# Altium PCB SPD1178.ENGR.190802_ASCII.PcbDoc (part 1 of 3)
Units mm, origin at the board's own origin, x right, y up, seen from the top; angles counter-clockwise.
Board outline 150 x 150 mm, 2 copper layers (Top Layer, Bottom Layer); 315 components, 164 nets, 838 pads, 882 vias.
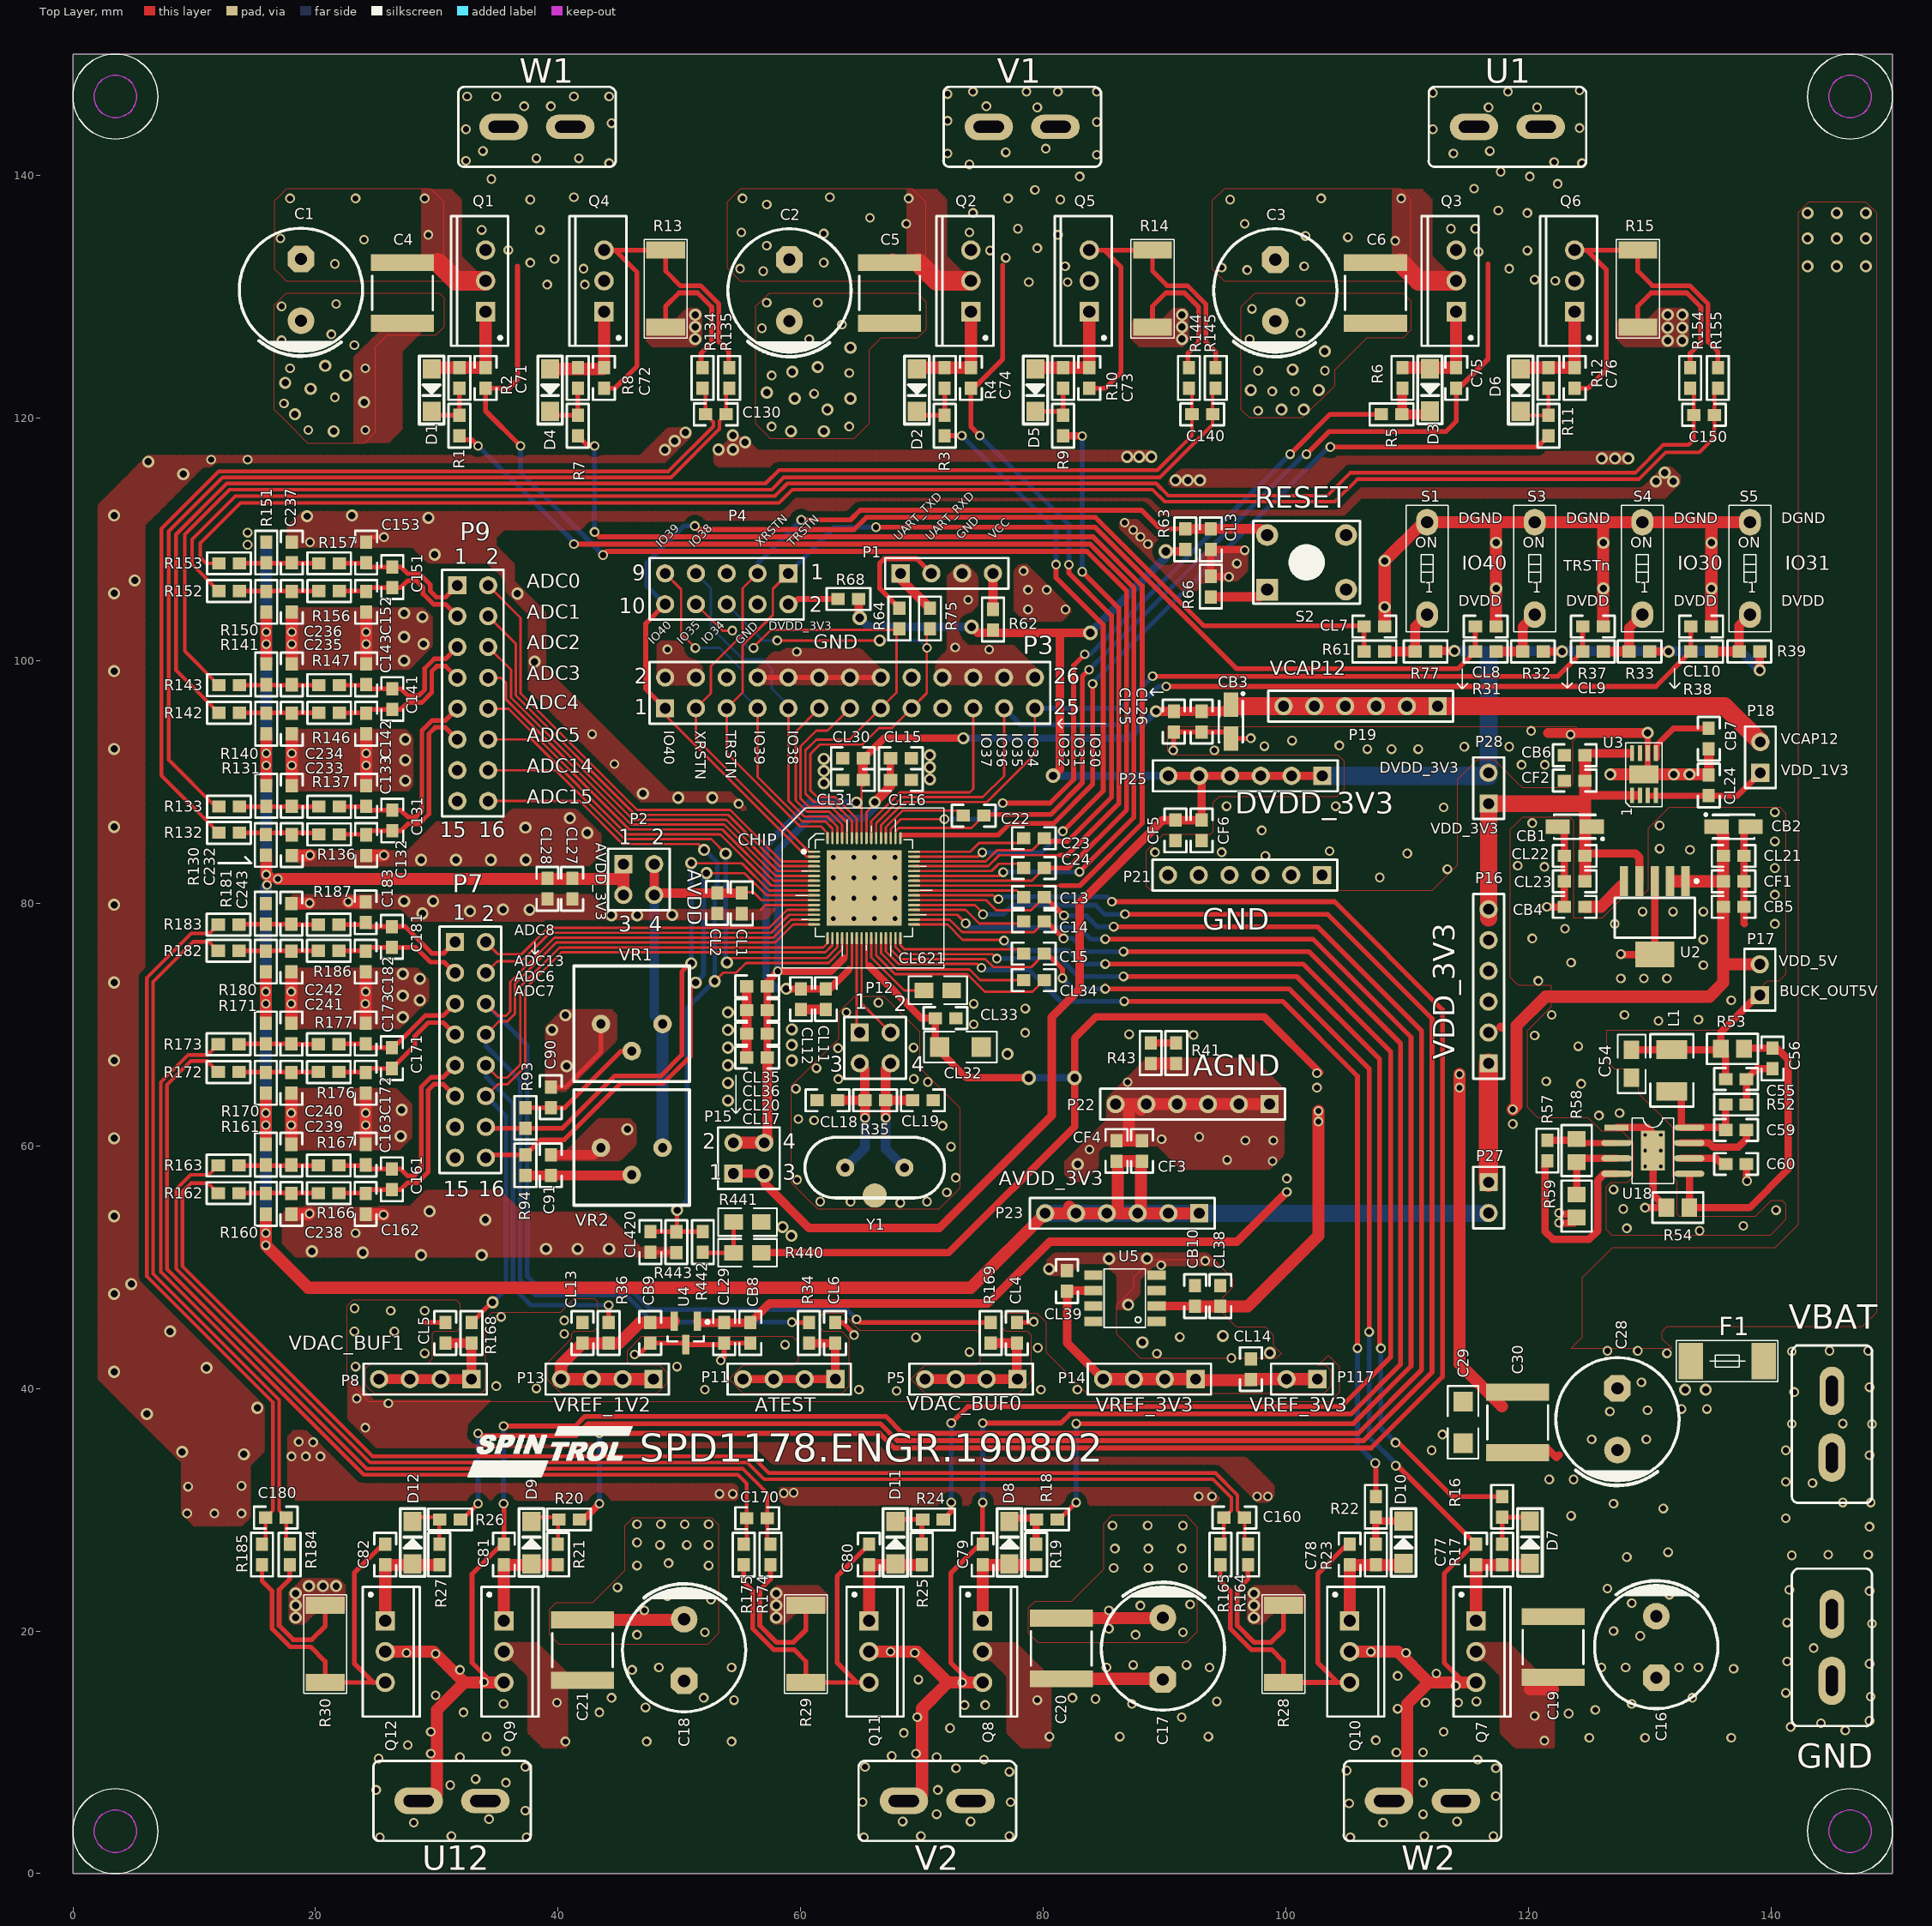
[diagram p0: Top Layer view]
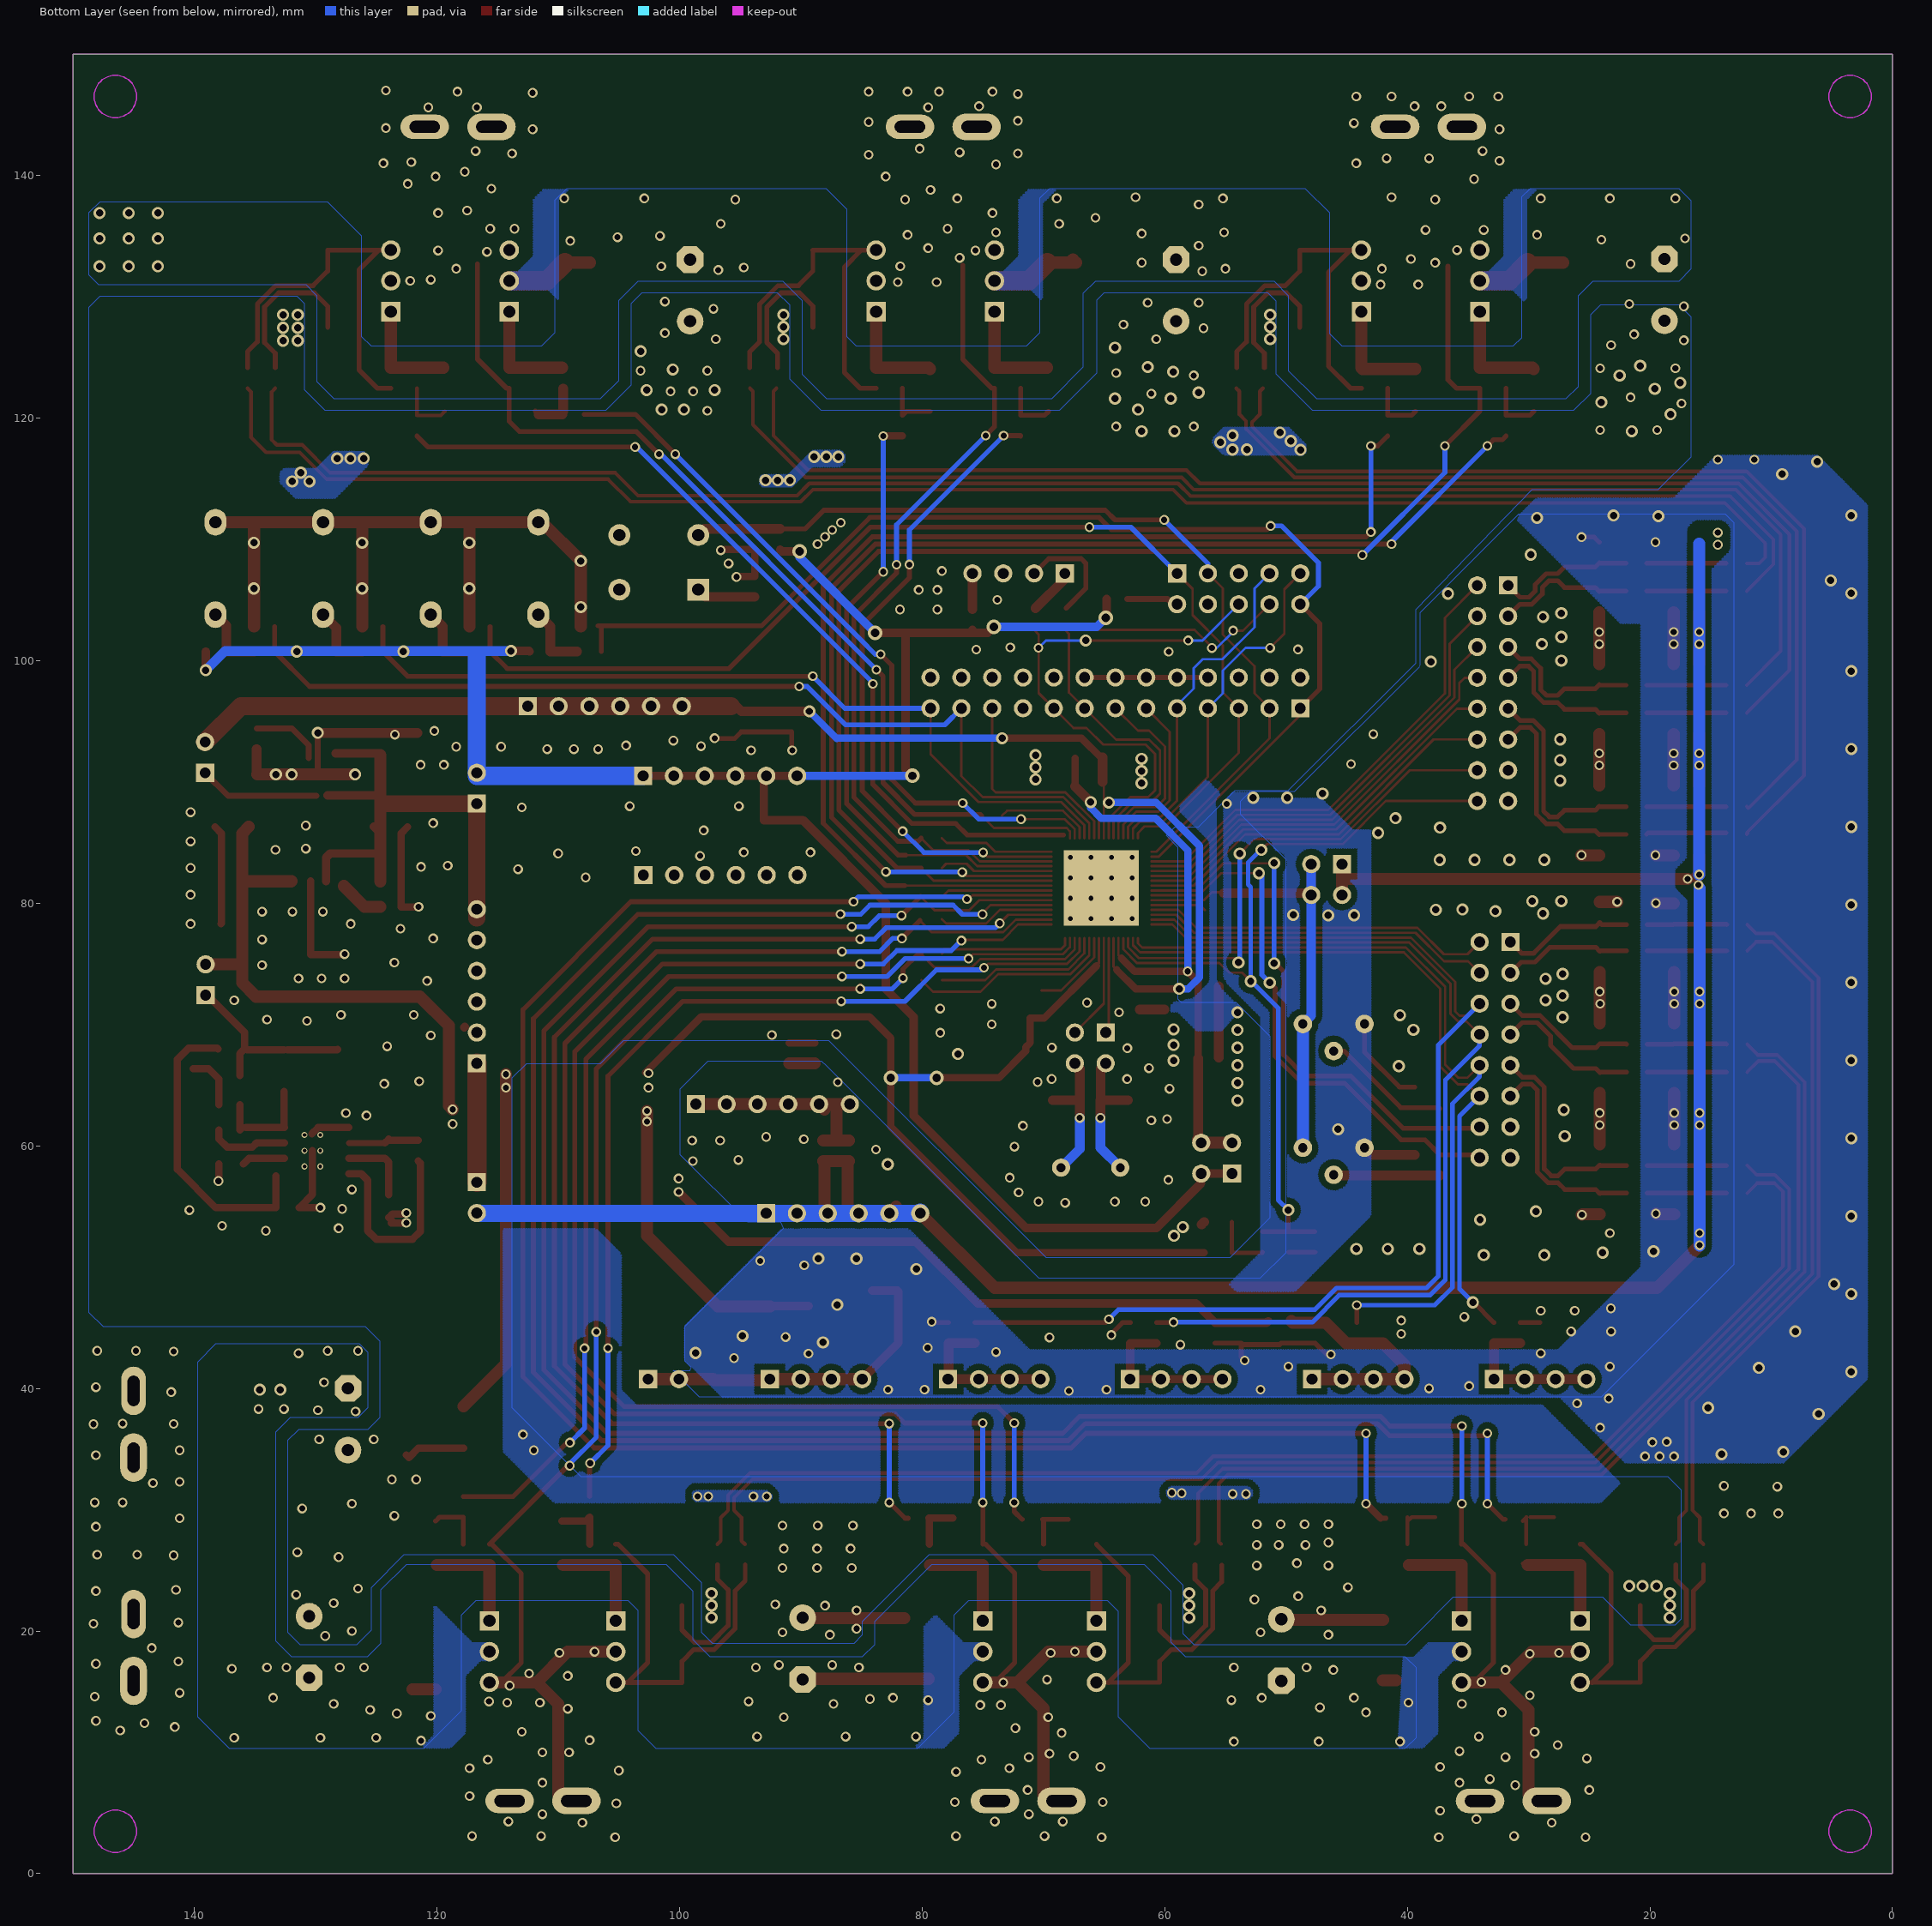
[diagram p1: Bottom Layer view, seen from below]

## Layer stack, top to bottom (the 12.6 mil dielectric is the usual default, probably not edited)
Top Solder: solder mask 0.0102, Solder Resist, Dk 3.5
Top Layer: signal copper 0.0356
Dielectric1: dielectric 0.32, FR-4, Dk 4.8
Bottom Layer: signal copper 0.0356
Bottom Solder: solder mask 0.0102, Solder Resist, Dk 3.5

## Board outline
0,0 0,150 150,150 150,0

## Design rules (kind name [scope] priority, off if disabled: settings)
AssemblyTestPointUsage [All] p0: scope1count=1 scope1_0_kind=Board scope1_0_value=Board scope2count=1 scope2_0_kind=Board scope2_0_value=Board commentlength=0
AssemblyTestpoint [All] p0: scope1count=1 scope1_0_kind=Board scope1_0_value=Board scope2count=1 scope2_0_kind=Board scope2_0_value=Board commentlength=0
Clearance 1 [All] p0: scope1count=1 scope1_0_kind=Board scope1_0_value=Board scope2count=1 scope2_0_kind=Board scope2_0_value=Board commentlength=0 gap=0.2
Clearance poly [All] p0 off: scope1count=1 scope1_0_kind=Board scope1_0_value=Board scope2count=1 scope2_0_kind=Board scope2_0_value=Board commentlength=48 gap=0.5 // Protel DXP Scope 1 Expression Was: InPolygon
Clearance [All] p0 off: scope1count=1 scope1_0_kind=Board scope1_0_value=Board scope2count=1 scope2_0_kind=Footprint scope2_0_value=OSC commentlength=60 gap=1.2 // Protel DXP Scope 1 Expression Was: InNamedPolygon('OSC')
Clearance [InNamedPolygon('OSC') vs HasFootprint('OSC')] p1: gap=1.2 ignorepadtopadclearanceinfootprint=FALSE except(0: Arc-Hole Track-Hole SMDPad-Hole THPad-Hole Via-Hole Fill-Hole Poly-Hole Region-Hole Text-Hole)
Clearance poly [InPolygon] p2: gap=0.5 ignorepadtopadclearanceinfootprint=FALSE except(0: Arc-Hole Track-Hole SMDPad-Hole THPad-Hole Via-Hole Fill-Hole Poly-Hole Region-Hole Text-Hole)
Clearance 1 [All] p3: gap=0.2 ignorepadtopadclearanceinfootprint=FALSE except(0: Arc-Hole Track-Hole SMDPad-Hole THPad-Hole Via-Hole Fill-Hole Poly-Hole Region-Hole Text-Hole)
ComponentClearance [All] p0 off: scope1count=1 scope1_0_kind=Board scope1_0_value=Board scope2count=1 scope2_0_kind=Board scope2_0_value=Board commentlength=0 gap=0.254 collisioncheckmode=3
ComponentClearance [All] p1 off: gap=0.254 collisioncheckmode=3 verticalgap=0.254 showdistances=FALSE
DiffPairsRouting [All] p0: scope1count=1 scope1_0_kind=Board scope1_0_value=Board scope2count=1 scope2_0_kind=Board scope2_0_value=Board commentlength=0
DiffPairsRouting [All] p1: maxlimit=1 minlimit=0.2 mostfreqgap=0.2 toplayer_minwidth=0.381 toplayer_maxwidth=0.381 toplayer_prefwidth=0.381 bottomlayer_minwidth=0.381 bottomlayer_maxwidth=0.381 bottomlayer_prefwidth=0.381 maxuncoupledlength=12.7
FabricationTestPointUsage [All] p0: scope1count=1 scope1_0_kind=Board scope1_0_value=Board scope2count=1 scope2_0_kind=Board scope2_0_value=Board commentlength=0 valid=0 allowmultiple=FALSE
FabricationTestpoint [All] p0: scope1count=1 scope1_0_kind=Board scope1_0_value=Board scope2count=1 scope2_0_kind=Board scope2_0_value=Board commentlength=0 side=3 testpointundercomponent=TRUE minsize=1.016 maxsize=2.54 preferedsize=1.524 minholesize=0 maxholesize=1.016 preferedholesize=0.813 testpointgrid=0.025
FanoutControl Fanout_BGA [All] p0 off: scope1count=1 scope1_0_kind=Board scope1_0_value=Board scope2count=1 scope2_0_kind=Board scope2_0_value=Board commentlength=69 // Protel DXP Scope 1 Expression Was: IsBGA   Fanout_BGA (Default Rule)
FanoutControl Fanout_LCC [All] p0 off: scope1count=1 scope1_0_kind=Board scope1_0_value=Board scope2count=1 scope2_0_kind=Board scope2_0_value=Board commentlength=69 // Protel DXP Scope 1 Expression Was: IsLCC   Fanout_LCC (Default Rule)
FanoutControl Fanout_SOIC [All] p0 off: scope1count=1 scope1_0_kind=Board scope1_0_value=Board scope2count=1 scope2_0_kind=Board scope2_0_value=Board commentlength=71 // Protel DXP Scope 1 Expression Was: IsSOIC   Fanout_SOIC (Default Rule)
FanoutControl Fanout_Small [All] p0 off: scope1count=1 scope1_0_kind=Board scope1_0_value=Board scope2count=1 scope2_0_kind=Board scope2_0_value=Board commentlength=84 // Protel DXP Scope 1 Expression Was: (CompPinCount < 5)   Fanout_Small (Default Rule)
FanoutControl Fanout_Default [All] p0: scope1count=1 scope1_0_kind=Board scope1_0_value=Board scope2count=1 scope2_0_kind=Board scope2_0_value=Board commentlength=30 // Fanout_Default (Default Rule)
FanoutControl Fanout_Small [All] p1 off: bgadir=Out bgaviamode=Centered fanoutstyle=Auto fanoutdirection=Alternating viagrid=0.025 // Protel DXP Scope 1 Expression Was: (CompPinCount < 5)   Fanout_Small (Default Rule)
FanoutControl Fanout_Default [All] p2: bgadir=Out bgaviamode=Centered fanoutstyle=Auto fanoutdirection=Alternating viagrid=0.025 // Fanout_Default (Default Rule)
FanoutControl Fanout_SOIC [All] p3 off: bgadir=Out bgaviamode=Centered fanoutstyle=Auto fanoutdirection=Alternating viagrid=0.025 // Protel DXP Scope 1 Expression Was: IsSOIC   Fanout_SOIC (Default Rule)
FanoutControl Fanout_BGA [All] p4 off: bgadir=Out bgaviamode=Centered fanoutstyle=Auto fanoutdirection=Alternating viagrid=0.025 // Protel DXP Scope 1 Expression Was: IsBGA   Fanout_BGA (Default Rule)
FanoutControl Fanout_LCC [All] p5 off: bgadir=Out bgaviamode=Centered fanoutstyle=Auto fanoutdirection=Alternating viagrid=0.025 // Protel DXP Scope 1 Expression Was: IsLCC   Fanout_LCC (Default Rule)
Height [All] p0 off: scope1count=1 scope1_0_kind=Board scope1_0_value=Board scope2count=1 scope2_0_kind=Board scope2_0_value=Board commentlength=0
Height [All] p1 off: minheight=0 maxheight=25.4 prefheight=12.7
HoleSize [All] p0: scope1count=1 scope1_0_kind=Board scope1_0_value=Board scope2count=1 scope2_0_kind=Board scope2_0_value=Board commentlength=0 absolutevalues=TRUE maxlimit=5 minlimit=0.025 maxpercent=80.000 minpercent=20.000
HoleSize [All] p1: absolutevalues=TRUE maxlimit=5 minlimit=0.025 maxpercent=80.000 minpercent=20.000
HoleToHoleClearance [All] p0 off: scope1count=1 scope1_0_kind=Board scope1_0_value=Board scope2count=1 scope2_0_kind=Board scope2_0_value=Board commentlength=0
HoleToHoleClearance [All] p1 off: gap=0 allowstackedmicrovias=FALSE
LayerPairs [All] p0: scope1count=1 scope1_0_kind=Board scope1_0_value=Board scope2count=1 scope2_0_kind=Board scope2_0_value=Board commentlength=0 enforce=TRUE
MinimumSolderMaskSliver [All] p0 off: scope1count=1 scope1_0_kind=Board scope1_0_value=Board scope2count=1 scope2_0_kind=Board scope2_0_value=Board commentlength=0
MinimumSolderMaskSliver [All] p1 off: minsoldermaskwidth=0.254
NetAntennae [All] p0: scope1count=1 scope1_0_kind=Board scope1_0_value=Board scope2count=1 scope2_0_kind=Board scope2_0_value=Board commentlength=0
PasteMaskExpansion [All] p0: scope1count=1 scope1_0_kind=Board scope1_0_value=Board scope2count=1 scope2_0_kind=Board scope2_0_value=Board commentlength=0 expansion=0
PlaneClearance [All] p0 off: scope1count=1 scope1_0_kind=Board scope1_0_value=Board scope2count=1 scope2_0_kind=Board scope2_0_value=Board commentlength=0 clearance=0.508
PlaneClearance [All] p1 off: clearance=0.508
PlaneConnect [All] p0: scope1count=1 scope1_0_kind=Board scope1_0_value=Board scope2count=1 scope2_0_kind=Board scope2_0_value=Board commentlength=0 planeconnectstyle=Direct reliefexpansion=0.508 reliefentries=4 reliefconductorwidth=0.254 reliefairgap=0.254
PlaneConnect [All] p1: planeconnectstyle=Direct reliefexpansion=0.508 reliefentries=4 reliefconductorwidth=0.254 reliefairgap=0.254
PolygonConnect [All] p0: scope1count=1 scope1_0_kind=Board scope1_0_value=Board scope2count=1 scope2_0_kind=Board scope2_0_value=Board commentlength=0 connectstyle=Direct reliefconductorwidth=0.254 reliefentries=4 polygonreliefangle="90 Angle"
PolygonConnect [All] p1: connectstyle=Direct reliefconductorwidth=0.254 reliefentries=4 polygonreliefangle="90 Angle" airgapwidth=0.254
RoutingCorners [All] p0: scope1count=1 scope1_0_kind=Board scope1_0_value=Board scope2count=1 scope2_0_kind=Board scope2_0_value=Board commentlength=0 cornerstyle=45-Degree minsetback=2.54 maxsetback=2.54
RoutingLayers [All] p0: scope1count=1 scope1_0_kind=Board scope1_0_value=Board scope2count=1 scope2_0_kind=Board scope2_0_value=Board commentlength=0 top layer=Automatic bottom layer=Automatic
RoutingPriority [All] p1: routingpriority=4
RoutingPriority [All] p4: scope1count=1 scope1_0_kind=Board scope1_0_value=Board scope2count=1 scope2_0_kind=Board scope2_0_value=Board commentlength=0
RoutingTopology [All] p0: scope1count=1 scope1_0_kind=Board scope1_0_value=Board scope2count=1 scope2_0_kind=Board scope2_0_value=Board commentlength=0 topology=Shortest
RoutingVias [All] p0: scope1count=1 scope1_0_kind=Board scope1_0_value=Board scope2count=1 scope2_0_kind=Board scope2_0_value=Board commentlength=0 holewidth=0.4 width=0.8 viastyle="Through Hole" minholewidth=0.1 minwidth=0.6 maxholewidth=2 maxwidth=3
RoutingVias [All] p1: holewidth=0.4 width=0.8 viastyle="Through Hole" minholewidth=0.1 minwidth=0.6 maxholewidth=2 maxwidth=3
ShortCircuit [All] p0: scope1count=1 scope1_0_kind=Board scope1_0_value=Board scope2count=1 scope2_0_kind=Board scope2_0_value=Board commentlength=0 allowed=FALSE
SilkToBoardRegionClearance [All] p0: scope1count=1 scope1_0_kind=Board scope1_0_value=Board scope2count=1 scope2_0_kind=Board scope2_0_value=Board commentlength=0
SilkToSilkClearance [All] p0 off: scope1count=1 scope1_0_kind=Board scope1_0_value=Board scope2count=1 scope2_0_kind=Board scope2_0_value=Board commentlength=0
SilkToSilkClearance [All] p1 off: silktosilkclearance=0.254
SilkToSolderMaskClearance SilkscreenOverComponentPads [All] p0 off: scope1count=1 scope1_0_kind=Board scope1_0_value=Board scope2count=1 scope2_0_kind=Board scope2_0_value=Board commentlength=44 // Protel DXP Scope 1 Expression Was: IsPad
SilkToSolderMaskClearance SilkscreenOverComponentPads [IsPad] p1 off: minsilkscreentomaskgap=0.254 clearancetoexposedcopper=TRUE
SolderMaskExpansion [All] p0: scope1count=1 scope1_0_kind=Board scope1_0_value=Board scope2count=1 scope2_0_kind=Board scope2_0_value=Board commentlength=0 expansion=0.102
SolderMaskExpansion [All] p1: expansion=0.102 istentingtop=FALSE
UnRoutedNet [All] p0: scope1count=1 scope1_0_kind=Board scope1_0_value=Board scope2count=1 scope2_0_kind=Board scope2_0_value=Board commentlength=0
UnpouredPolygon [All] p0: scope1count=1 scope1_0_kind=Board scope1_0_value=Board scope2count=1 scope2_0_kind=Board scope2_0_value=Board commentlength=0
Width [All] p0: scope1count=1 scope1_0_kind=Board scope1_0_value=Board scope2count=1 scope2_0_kind=Board scope2_0_value=Board commentlength=0 maxlimit=5 minlimit=0.2 preferedwidth=0.4
Width [All] p1: maxlimit=5 minlimit=0.2 preferedwidth=0.4
14 further rules are at their usual default settings.

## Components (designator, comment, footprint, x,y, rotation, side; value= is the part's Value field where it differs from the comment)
C1 "47uF/160V" RB5.0/10 18.8,133.1 r90 top
C2 "47uF/160V" RB5.0/10 59.068,133.05 r90 top
C3 "47uF/160V" RB5.0/10 99.119,133.05 r90 top
C4 "2.2uF/250V" 2220 27.17,130.307 r270 top
C5 "2.2uF/250V" 2220 67.323,130.307 r270 top
C6 "2.2uF/250V" 2220 107.374,130.307 r270 top
C13 "100nF/100V" C0603[1608] 79.22,80.5 r0 top
C14 "100nF/100V" C0603[1608] 79.22,78.51 r0 top
C15 "100nF/100V" C0603[1608] 79.21,75.85 r0 top
C16 "47uF/160V" RB5.0/10 130.523,16.145 r270 top
C17 "47uF/160V" RB5.0/10 89.853,16.018 r270 top
C18 "47uF/160V" RB5.0/10 50.386,15.891 r270 top
C19 "2.2uF/250V" 2220 122.014,18.685 r90 top
C20 "2.2uF/250V" 2220 81.471,18.558 r90 top
C21 "2.2uF/250V" 2220 42.004,18.431 r90 top
C22 "100nF/100V" C0603[1608] 74.25,87.22 r0 top
C23 "100nF/100V" C0603[1608] 79.22,85.36 r0 top
C24 "100nF/100V" C0603[1608] 79.22,82.9 r0 top
C28 "47uF/160V" RB5.0/10 127.323,40 r90 top
C29 "47nF/200V" 1206 114.6,37.2 r270 top
C30 "2.2uF/250V" 2220 119.1,37.2 r270 top
C54 "22uF" 0805 128.49,66.76 r270 top
C55 "470pF" C0603[1608] 137.1,65.5 r180 top
C56 "10nF" C0603[1608] 140.1,67.2 r90 top
C59 "10nF" C0603[1608] 137.1,61.3 r180 top
C60 "1uF/16V" C0603[1608] 137.1,58.5 r180 top
C71 "1nF" C0603[1608] 34.019,123.301 r270 top
C72 "1nF" C0603[1608] 43.782,123.301 r270 top
C73 "1nF" C0603[1608] 83.787,123.301 r270 top
C74 "1nF" C0603[1608] 74.024,123.301 r270 top
C75 "1nF" C0603[1608] 114.029,123.301 r270 top
C76 "1nF" C0603[1608] 123.792,123.301 r270 top
C77 "1nF" C0603[1608] 115.664,26.305 r90 top
C78 "1nF" C0603[1608] 105.25,26.305 r90 top
C79 "1nF" C0603[1608] 74.994,26.305 r90 top
C80 "1nF" C0603[1608] 65.626,26.305 r90 top
C81 "1nF" C0603[1608] 35.527,26.305 r90 top
C82 "1nF" C0603[1608] 25.748,26.305 r90 top
C90 "100nF" C0603[1608] 39.4,64 r270 top
C91 "100nF" C0603[1608] 39.4,58.4 r270 top
C130 "1nF" C0603[1608] 53,120.3 r180 top
C131 "22pF" C0603[1608] 26.331,86.819 r270 top
C132 "22pF" C0603[1608] 24.172,84.787 r270 top
C133 "22pF" C0603[1608] 24.172,88.851 r90 top
C140 "1nF" C0603[1608] 93.1,120.3 r180 top
C141 "22pF" C0603[1608] 26.331,96.833 r270 top
C142 "22pF" C0603[1608] 24.172,94.801 r270 top
C143 "22pF" C0603[1608] 24.172,98.865 r90 top
C150 "1nF" C0603[1608] 134.463,120.253 r180 top
C151 "22pF" C0603[1608] 26.331,106.874 r270 top
C152 "22pF" C0603[1608] 24.172,104.842 r270 top
C153 "22pF" C0603[1608] 24.172,108.906 r90 top
C160 "1nF" C0603[1608] 95.741,29.353 r0 top
C161 "22pF" C0603[1608] 26.293,57.24 r270 top
C162 "22pF" C0603[1608] 24.134,55.208 r270 top
C163 "22pF" C0603[1608] 24.134,59.272 r90 top
C170 "1nF" C0603[1608] 56.4,29.3 r0 top
C171 "22pF" C0603[1608] 26.293,67.227 r270 top
C172 "22pF" C0603[1608] 24.134,65.195 r270 top
C173 "22pF" C0603[1608] 24.134,69.259 r90 top
C180 "1nF" C0603[1608] 16.731,29.353 r0 top
C181 "22pF" C0603[1608] 26.293,77.222 r270 top
C182 "22pF" C0603[1608] 24.134,75.19 r270 top
C183 "22pF" C0603[1608] 24.134,79.254 r90 top
C232 "22pF" C0603[1608] 18.042,84.787 r270 top
C233 "22pF" C0603[1608] 18.042,88.851 r270 top
C234 "22pF" C0603[1608] 18.042,94.801 r270 top
C235 "22pF" C0603[1608] 18.042,98.86 r270 top
C236 "22pF" C0603[1608] 18.042,104.842 r270 top
C237 "22pF" C0603[1608] 18.042,108.906 r270 top
C238 "22pF" C0603[1608] 18.004,55.208 r270 top
C239 "22pF" C0603[1608] 18.004,59.272 r270 top
C240 "22pF" C0603[1608] 18.004,65.195 r270 top
C241 "22pF" C0603[1608] 18.004,69.259 r270 top
C242 "22pF" C0603[1608] 18.004,75.19 r270 top
C243 "22pF" C0603[1608] 18.004,79.127 r270 top
CB1 "10uF/10V" TC3216-A 123.8,86.3 r180 top
CB2 "10uF/10V" TC3216-A 136.9,86.3 r0 top
CB3 "10uF/10V" TC3216-A 95.455,94.968 r270 top
CB4 "10nF" C0603[1608] 123.8,79.7 r180 top
CB5 "2.2uF/10V" C0603[1608] 136.9,79.7 r0 top
CB6 "2.2uF/10V" C0603[1608] 123.8,92.2 r180 top
CB7 "10nF" C0603[1608] 134.85,93.56 r270 top
CB8 "100nF" C0603[1608] 55.847,44.577 r90 top
CB9 "100nF" C0603[1608] 47.592,44.577 r90 top
CB10 "100nF" C0603[1608] 92.506,47.614 r270 top
CF1 "100nF" C0603[1608] 136.9,81.8 r0 top
CF2 "100nF" C0603[1608] 123.8,90.1 r180 top
CF3 "100nF" C0603[1608] 88.13,59.58 r90 top
CF4 "2.2uF/10V" C0603[1608] 86.03,59.58 r90 top
CF5 "100nF" C0603[1608] 90.883,86.003 r270 top
CF6 "2.2uF/10V" C0603[1608] 93.042,86.003 r270 top
CHIP "SPD1098D" QFN64L_201707 65.22,81.25 r0 top
CL1 "4.7uF/10V" C0603[1608] 55.133,79.987 r90 top
CL2 "100nF" C0603[1608] 53.11,80.01 r90 top
CL3 "1uF/16V" C0603[1608] 93.8,110 r90 top
CL4 "100nF" C0603[1608] 77.818,44.577 r90 top
CL5 "100nF" C0603[1608] 30.701,44.577 r90 top
CL6 "100nF" C0603[1608] 62.832,44.577 r90 top
CL7 "" C0603[1608] 107.29,102.81 r0 top
CL8 "100nF" C0603[1608] 116.46,102.81 r0 top
CL9 "100nF" C0603[1608] 125.3,102.81 r0 top
CL10 "100nF" C0603[1608] 134.22,102.81 r0 top
CL11 "22nF/50V" C0603[1608] 62.07,72.09 r90 top
CL12 "2.2uF/10V" C0603[1608] 60.02,72.09 r90 top
CL13 "100nF" C0603[1608] 42.004,44.577 r270 top
CL14 "100nF" C0603[1608] 97.11,41.59 r270 top
CL15 "4.7uF/10V" C0603[1608] 68.25,91.95 r180 top
CL16 "100nF" C0603[1608] 68.25,90.16 r180 top
CL17 "4.7uF/10V" C0603[1608] 56.4,67.28 r0 top
CL18 "20pF" C0603[1608] 62.197,63.754 r0 top
CL19 "20pF" C0603[1608] 70.071,63.754 r180 top
CL20 "100nF" C0603[1608] 56.4,69.235 r0 top
CL21 "4.7uF/10V" C0603[1608] 136.9,83.9 r0 top
CL22 "4.7uF/10V" C0603[1608] 123.8,83.9 r180 top
CL23 "4.7uF/10V" C0603[1608] 123.8,81.8 r180 top
CL24 "4.7uF/10V" C0603[1608] 134.85,89.71 r90 top
CL25 "100nF" C0603[1608] 90.756,94.968 r270 top
CL26 "100nF" C0603[1608] 93.042,94.968 r270 top
CL27 "2.2uF" C0603[1608] 41.165,81.19 r90 top
CL28 "10nF" C0603[1608] 39.12,81.19 r90 top
CL29 "1uF/16V" C0603[1608] 53.688,44.577 r90 top
CL30 "10nF" C0603[1608] 64.3,91.95 r0 top
CL31 "100nF" C0603[1608] 64.3,90.16 r0 top
CL32 "2.2uF/100V" 1206 73.16,68.14 r180 top
CL33 "100nF/100V" C0603[1608] 71.93,70.52 r180 top
CL34 "22nF/50V" C0603[1608] 79.215,73.66 r0 top
CL35 "4.7uF/10V" C0603[1608] 56.4,73.145 r0 top
CL36 "100nF" C0603[1608] 56.4,71.19 r0 top
CL38 "1uF/16V" C0603[1608] 94.586,47.614 r270 top
CL39 "1uF/16V" C0603[1608] 81.95,48.85 r270 top
CL420 "1nF" C0603[1608] 47.608,52.07 r90 top
CL621 "2.2uF/30V" 0805 71.3,72.82 r180 top
D1 "IN4148W-E3-08" LL-34 29.574,122.285 r90 top
D2 "IN4148W-E3-08" LL-34 69.579,122.285 r90 top
D3 "IN4148W-E3-08" LL-34 111.87,122.3 r90 top
D4 "IN4148W-E3-08" LL-34 39.337,122.285 r90 top
D5 "IN4148W-E3-08" LL-34 79.342,122.285 r90 top
D6 "IN4148W-E3-08" LL-34 119.347,122.285 r90 top
D7 "IN4148W-E3-08" LL-34 120.109,27.321 r270 top
D8 "IN4148W-E3-08" LL-34 77.2,27.3 r270 top
D9 "IN4148W-E3-08" LL-34 37.8,27.3 r270 top
D10 "IN4148W-E3-08" LL-34 109.695,27.321 r270 top
D11 "IN4148W-E3-08" LL-34 67.8,27.3 r270 top
D12 "IN4148W-E3-08" LL-34 28,27.3 r270 top
F1 "36V/30A" F3 139.38,42.26 r180 top
GND "250插片" PIN_L 145,21.4 r270 top
L1 "47uH 1.0A" 1210R 131.8,64.5 r90 top
P1 "单排插座2.54*4" HDR1X4 68.225,107.188 r0 top
P2 "双排插针2.54*2" HDR2X2 45.38,83.22 r270 top
P3 "双排插针2.54*13" HDR2X13 48.818,96.069 r0 top
P4 "双排插针2.54*5" HDR2X5 58.978,107.188 r180 top locked
P5 "单排插针2.54*4" HDR1X4 77.857,40.767 r180 top
P7 "双排插针2.54*8" HDR2X8 31.5,76.8 r270 top
P8 "单排插针2.54*4" HDR1X4 32.857,40.767 r180 top
P9 "双排插针2.54*8" HDR2X8 31.692,106.2 r270 top
P11 "单排插针2.54*4" HDR1X4 62.857,40.767 r180 top
P12 "双排插针2.54*2" HDR2X2 64.864,69.342 r270 top
P13 "单排插针2.54*4" HDR1X4 47.857,40.767 r180 top
P14 "单排插针2.54*4" HDR1X4 92.55,40.767 r180 top
P15 "双排插针2.54*2" HDR2X2 54.45,57.71 r0 top
P16 "单排插针2.54*6" HDR1X6 116.7,66.8 r90 top
P17 "单排插针2.54*2" HDR1X2 139.06,72.421 r90 top
P18 "单排插针2.54*2" HDR1X2 139.105,90.75 r90 top
P19 "单排插针2.54*6" HDR1X6 112.5,96.24 r180 top
P21 "单排插针2.54*6" HDR1X6 102.97,82.32 r180 top
P22 "单排插针2.54*6" HDR1X6 98.65,63.44 r180 top
P23 "单排插针2.54*6" HDR1X6 92.85,54.44 r180 top
P25 "单排插针2.54*6" HDR1X6 103,90.5 r180 top
P27 "单排插针2.54*2" HDR1X2 116.7,57 r270 top
P28 "单排插针2.54*2" HDR1X2 116.7,88.21 r90 top
P117 "单排插针2.54*2" HDR1X2 102.583,40.767 r180 top
Q1 "IRF1010E" TO-220AB 34.019,131.302 r90 top
Q2 "IRF1010E" TO-220AB 74.024,131.302 r90 top
Q3 "IRF1010E" TO-220AB 114.029,131.302 r90 top
Q4 "IRF1010E" TO-220AB 43.782,131.302 r90 top
Q5 "IRF1010E" TO-220AB 83.787,131.302 r90 top
Q6 "IRF1010E" TO-220AB 123.792,131.302 r90 top
Q7 "IRF1010E" TO-220AB 115.664,18.304 r270 top
Q8 "IRF1010E" TO-220AB 74.994,18.304 r270 top
Q9 "IRF1010E" TO-220AB 35.527,18.304 r270 top
Q10 "IRF1010E" TO-220AB 105.25,18.304 r270 top
Q11 "IRF1010E" TO-220AB 65.626,18.304 r270 top
Q12 "IRF1010E" TO-220AB 25.748,18.304 r270 top
R1 "22R" R0603[1608] 31.86,119.364 r90 top
R2 "22R" R0603[1608] 31.86,123.301 r90 top
R3 "22R" R0603[1608] 71.865,119.364 r90 top
R4 "22R" R0603[1608] 71.865,123.301 r90 top
R5 "22R" R0603[1608] 108.7,120.3 r0 top
R6 "22R" R0603[1608] 109.6,123.3 r90 top
R7 "22R" R0603[1608] 41.623,119.364 r90 top
R8 "22R" R0603[1608] 41.623,123.301 r90 top
R9 "22R" R0603[1608] 81.628,119.364 r90 top
R10 "22R" R0603[1608] 81.628,123.301 r90 top
R11 "22R" R0603[1608] 121.633,119.364 r90 top
R12 "22R" R0603[1608] 121.633,123.301 r90 top
R13 "0.005R /1W 1% 50ppm" 2512 48.862,130.667 r90 top
R14 "0.005R /1W 1% 50ppm" 2512 88.994,130.667 r90 top
R15 "0.005R /1W 1% 50ppm" 2512 128.999,130.667 r90 top
R16 "22R" R0603[1608] 117.823,30.242 r270 top
R17 "22R" R0603[1608] 117.823,26.305 r270 top
R18 "22R" R0603[1608] 80.3,29.2 r180 top
R19 "22R" R0603[1608] 79.4,26.3 r270 top
R20 "22R" R0603[1608] 40.9,29.2 r180 top
R21 "22R" R0603[1608] 39.986,26.305 r270 top
R22 "22R" R0603[1608] 107.409,30.242 r270 top
R23 "22R" R0603[1608] 107.409,26.305 r270 top
R24 "22R" R0603[1608] 70.9,29.2 r180 top
R25 "22R" R0603[1608] 69.985,26.305 r270 top
R26 "22R" R0603[1608] 31.1,29.2 r180 top
R27 "22R" R0603[1608] 30.207,26.305 r270 top
R28 "0.005R /1W 1% 50ppm" 2512 99.789,18.939 r270 top
R29 "0.005R /1W 1% 50ppm" 2512 60.419,18.939 r270 top
R30 "0.005R /1W 1% 50ppm" 2512 20.795,18.939 r270 top
R31 "2K" R0603[1608] 116.46,100.75 r0 top
R32 "4.7K" R0603[1608] 120.36,100.75 r180 top
R33 "4.7K" R0603[1608] 129.14,100.75 r180 top
R34 "NI" R0603[1608] 60.673,44.577 r90 top
R35 "NI" R0603[1608] 66.134,63.754 r0 top
R36 "NI" R0603[1608] 44.163,44.577 r90 top
R37 "2K" R0603[1608] 125.3,100.75 r0 top
R38 "2K" R0603[1608] 134.22,100.75 r0 top
R39 "4.7K" R0603[1608] 138.2,100.75 r180 top
R41 "0R" R0603[1608] 90.95,67.64 r90 top
R43 "0R" R0603[1608] 88.85,67.64 r90 top
R52 "820K" R0603[1608] 137.1,63.4 r180 top
R53 "36K" R0805[2012] 136.8,68 r0 top
R54 "12K" R0805[2012] 132.3,54.9 r180 top
R57 "470K" R0603[1608] 121.548,59.605 r270 top
R58 "56K" R0805[2012] 123.961,59.605 r270 top
R59 "10K" R0805[2012] 123.961,55.033 r270 top
R61 "2K" R0603[1608] 107.29,100.75 r0 top
R62 "0R" R0603[1608] 75.845,103.378 r270 top
R63 "4.7K" R0603[1608] 91.7,110 r270 top
R64 "0R" R0603[1608] 68.13,103.47 r90 top
R66 "22R" R0603[1608] 93.8,106.1 r270 top
R68 "0R" R0603[1608] 63.93,105.08 r0 top
R75 "0R" R0603[1608] 70.65,103.47 r90 top
R77 "4.7K" R0603[1608] 111.5,100.75 r180 top
R93 "1K" R0603[1608] 37.3,62.3 r270 top
R94 "1K" R0603[1608] 37.3,58.4 r90 top
R130 "2K" R0603[1608] 15.9,84.8 r270 top
R131 "2K" R0603[1608] 15.942,88.851 r90 top
R132 "2K" R0603[1608] 12.869,85.803 r0 top
R133 "2K" R0603[1608] 12.869,87.962 r0 top
R134 "1R" R0603[1608] 51.9,123.3 r270 top
R135 "1R" R0603[1608] 54.1,123.3 r270 top
R136 "2K" R0603[1608] 21.124,85.676 r0 top
R137 "2K" R0603[1608] 21.124,87.962 r0 top
R140 "2K" R0603[1608] 15.942,94.801 r270 top
R141 "2K" R0603[1608] 15.942,98.86 r90 top
R142 "2K" R0603[1608] 12.869,95.69 r0 top
R143 "2K" R0603[1608] 12.869,97.976 r0 top
R144 "1R" R0603[1608] 92,123.3 r270 top
R145 "1R" R0603[1608] 94.2,123.3 r270 top
R146 "2K" R0603[1608] 21.124,95.69 r0 top
R147 "2K" R0603[1608] 21.124,97.976 r0 top
R150 "2K" R0603[1608] 15.942,104.842 r270 top
R151 "2K" R0603[1608] 15.942,108.906 r90 top
R152 "2K" R0603[1608] 12.869,105.731 r0 top
R153 "2K" R0603[1608] 12.869,108.017 r0 top
R154 "1R" R0603[1608] 133.32,123.301 r270 top
R155 "1R" R0603[1608] 135.606,123.301 r270 top
R156 "2K" R0603[1608] 21.124,105.731 r0 top
R157 "2K" R0603[1608] 21.124,108.017 r0 top
R160 "2K" R0603[1608] 15.904,55.208 r270 top
R161 "2K" R0603[1608] 15.904,59.272 r90 top
R162 "2K" R0603[1608] 12.831,56.097 r0 top
R163 "2K" R0603[1608] 12.831,58.383 r0 top
R164 "1R" R0603[1608] 96.884,26.305 r90 top
R165 "1R" R0603[1608] 94.598,26.305 r90 top
R166 "2K" R0603[1608] 21.086,56.097 r0 top
R167 "2K" R0603[1608] 21.086,58.383 r0 top
R168 "NI" R0603[1608] 32.86,44.577 r90 top
R169 "NI" R0603[1608] 75.659,44.577 r90 top
R170 "2K" R0603[1608] 15.904,65.195 r270 top
R171 "2K" R0603[1608] 15.904,69.259 r90 top
R172 "2K" R0603[1608] 12.831,66.084 r0 top
R173 "2K" R0603[1608] 12.831,68.37 r0 top
R174 "1R" R0603[1608] 57.5,26.3 r90 top
R175 "1R" R0603[1608] 55.3,26.3 r90 top
R176 "2K" R0603[1608] 21.086,66.084 r0 top
R177 "2K" R0603[1608] 21.086,68.37 r0 top
R180 "2K" R0603[1608] 15.904,75.19 r270 top
R181 "2K" R0603[1608] 15.904,79.127 r90 top
R182 "2K" R0603[1608] 12.831,76.079 r0 top
R183 "2K" R0603[1608] 12.831,78.238 r0 top
R184 "1R" R0603[1608] 17.874,26.305 r90 top
R185 "1R" R0603[1608] 15.588,26.305 r90 top
R186 "2K" R0603[1608] 21.086,76.079 r0 top
R187 "2K" R0603[1608] 21.086,78.238 r0 top
R440 "120K" 0805 55.609,51.181 r0 top
R441 "5.1K" 0805 55.609,53.721 r180 top
R442 "2K" R0603[1608] 51.926,52.07 r270 top (schematic designator R163)
R443 "100K" R0603[1608] 49.75,52.06 r270 top
S1 "DSIC01LH-P" S7.62*1 111.63,103.79 r90 top
S2 "SW-PB" SWITCH-4 101.7,108.1 r0 top
S3 "DSIC01LH-P" S7.62*1 120.503,103.79 r90 top
S4 "DSIC01LH-P" S7.62*1 129.377,103.79 r90 top
S5 "DSIC01LH-P" S7.62*1 138.25,103.79 r90 top
U1 "250插片" PIN_L 121,144 r180 top
U2 "TPS79633DCQ" TI-DCQ6_N 130.4,78.8 r270 top
U3 "TPS79613DRBR" TI-DRB8-2400X1650TP_V 129.5,90.62 r90 top
U4 "ADR280ARTZ-R2" ADI-RT-3_N 50.513,44.577 r270 top
U5 "LT1461DHS8-3.3#PBF" "S8 PACKAGE" 89.33,45.53 r90 top
U12 "250插片" PIN_L 34,6 r180 top
U18 "LM5017" DDA 127.244,61.51 r0 top
V1 "250插片" PIN_L 81,144 r180 top
V2 "250插片" PIN_L 74,6 r180 top
VBAT "250插片" PIN_L 145,39.8 r270 top
VR1 "10K" VR_3386_Knob 41.298,74.824 r0 top
VR2 "10K" VR_3386_Knob 41.298,64.624 r0 top
W1 "250插片" PIN_L 41,144 r180 top
W2 "250插片" PIN_L 114,6 r180 top
Y1 "OSC32MHz" OSC 66.1,58.2 r0 top

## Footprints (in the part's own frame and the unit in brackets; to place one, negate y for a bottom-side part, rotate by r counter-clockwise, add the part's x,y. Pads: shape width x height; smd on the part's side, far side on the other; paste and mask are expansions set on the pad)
0805 [mil]
  rect 60x50 smd: 1(-45,0) 2(45,0)
  silkscreen extent -95,-45 95,45
1206 [mm]
  rect 1.6x1.6 smd: 1(-1.715,0) 2(1.714,0)
  silkscreen extent -3,-1.27 3,1.27
1210R [mil]
  rect 60x100 smd: 1(0,0) 2(135,0)
  silkscreen extent -50,-70 185,70
2220 [mm] "Chip Capacitor, Body 5.7x5.0mm, IPC High Density"
  rect 1.4x5.2 smd: 1(-2.5,0) 2(2.5,0)
  silkscreen extent -1.4,-2.5 1.4,2.5
2512 [mm]
  rect 1.4x3.2 smd: 1(-3.175,0) 2(3.175,0)
  silkscreen extent -4.06,-1.78 4.06,1.78
ADI-RT-3_N [mm] "SOT23, 3-Leads, Body 2.9x1.3mm, Pitch 0.96mm, IPC Medium Density"
  rect 1.6x0.6 smd: 1(-0.96,0.96) 2(-0.96,-0.96) 3(0.96,0)
  silkscreen extent -1.02,-1.5 0.7,1.93
C0603[1608] [mm] "Chip Capacitor; Body 1.6 x 0.8 mm (LxW typ)"
  rect 1.1x1 smd: 1(-0.85,0) 2(0.85,0)
  silkscreen extent -1.8,-0.9 1.8,0.9
DDA [mm]
  rect 2x0.5 smd: 1(0,0)
  oval 2.5x0.5 smd: 2(0,-1.27) 3(0,-2.54) 4(0,-3.81) 5(6,-3.81) 6(6,-2.54) 7(6,-1.27) 8(6,0)
  rect 2x3.3 smd: 9(3,-1.9)
  silkscreen extent 1.3,-4.61 4.7,0.8
F3 [mm]
  rect 2x3 smd: 1(0,0) 2(6,0)
  silkscreen extent -1.15,-1.7 7.2,1.7
HDR1X2 [mm] "Connector; Header; 2 Position"
  rect 1.5x1.5 hole 0.9: 1(0,0)
  round 1.5 hole 0.9: 2(2.54,0)
  silkscreen extent -1.27,-1.27 3.81,1.27
HDR1X4 [mm] "Connector; Header; 4 Position"
  rect 1.5x1.5 hole 0.9: 1(0,0)
  round 1.5 hole 0.9: 2(2.54,0) 3(5.08,0) 4(7.62,0)
  silkscreen extent -1.27,-1.27 8.89,1.27
HDR1X6 [mm] "Connector; Header; 6 Position"
  rect 1.5x1.5 hole 0.9: 1(0,0)
  round 1.5 hole 0.9: 2(2.54,0) 3(5.08,0) 4(7.62,0) 5(10.16,0) 6(12.7,0)
  silkscreen extent -1.27,-1.27 13.97,1.27
HDR2X2 [mm] "Connector; Header; 2x2 Position"
  rect 1.5x1.5 hole 0.9: 1(0,0)
  round 1.5 hole 0.9: 2(0,2.54) 3(2.54,0) 4(2.54,2.54)
  silkscreen extent -1.27,-1.27 3.81,3.81
HDR2X5 [mm] "Connector; Header; 5x2 Position"
  rect 1.5x1.5 hole 0.9: 1(0,0)
  round 1.5 hole 0.9: 2(0,2.54) 3(2.54,0) 4(2.54,2.54) 5(5.08,0) 6(5.08,2.54) 7(7.62,0) 8(7.62,2.54) 9(10.16,0) 10(10.16,2.54)
  silkscreen extent -1.27,-1.27 11.43,3.81
HDR2X8 [mm] "Connector; Header; 8x2 Position"
  rect 1.5x1.5 hole 0.9: 1(0,0)
  round 1.5 hole 0.9: 2(0,2.54) 3(2.54,0) 4(2.54,2.54) 5(5.08,0) 6(5.08,2.54) 7(7.62,0) 8(7.62,2.54) 9(10.16,0) 10(10.16,2.54) 11(12.7,0) 12(12.7,2.54) 13(15.24,0) 14(15.24,2.54) 15(17.78,0) 16(17.78,2.54)
  silkscreen extent -1.27,-1.27 19.05,3.81
HDR2X13 [mm] "Connector; Header; 13x2 Position"
  rect 1.5x1.5 hole 0.9: 1(0,0)
  round 1.5 hole 0.9: 2(0,2.54) 3(2.54,0) 4(2.54,2.54) 5(5.08,0) 6(5.08,2.54) 7(7.62,0) 8(7.62,2.54) 9(10.16,0) 10(10.16,2.54) 11(12.7,0) 12(12.7,2.54) 13(15.24,0) 14(15.24,2.54) 15(17.78,0) 16(17.78,2.54) 17(20.32,0) 18(20.32,2.54) 19(22.86,0) 20(22.86,2.54) 21(25.4,0) 22(25.4,2.54) 23(27.94,0) 24(27.94,2.54) 25(30.48,0) 26(30.48,2.54)
  silkscreen extent -1.27,-1.27 31.75,3.81
LL-34 [mm]
  rect 1.6x1.5 smd: 1(1.758,0) 2(-1.742,0)
  silkscreen extent -2.79,-1.02 2.8,1.02
OSC [mm] "CRYSTAL 32.0000MHZ 20PF T/H"
  round 1.5 hole 0.73: 1(-2.44,0) 2(2.44,0)
  silkscreen extent -5.75,-2.5 5.75,2.5
PIN_L [mm]
  oval 4x2 hole 1 slot 2.5 at 0 deg: 1(0,0)
  oval 4x2.2 hole 1 slot 2.5 at 0 deg: 1(5.5,0)
  silkscreen extent -3.75,-3.3 9.24,3.3
QFN64L_201707 [mm]
  oval 1x0.2 smd: 1(-4.126,2.997) 2(-4.126,2.597) 3(-4.126,2.197) 4(-4.126,1.797) 5(-4.126,1.397) 6(-4.126,0.997) 7(-4.126,0.597) 8(-4.126,0.197) 9(-4.126,-0.203) 10(-4.126,-0.603) 11(-4.126,-1.003) 12(-4.126,-1.403) 13(-4.126,-1.803) 14(-4.126,-2.203) 15(-4.126,-2.603) 16(-4.126,-3.003) 33(4.113,-3.003) 34(4.113,-2.603) 35(4.113,-2.203) 36(4.113,-1.803) 37(4.113,-1.403) 38(4.113,-1.003) 39(4.113,-0.603) 40(4.113,-0.203) 41(4.113,0.197) 42(4.113,0.597) 43(4.113,0.997) 44(4.113,1.397) 45(4.113,1.797) 46(4.113,2.197) 47(4.113,2.597) 48(4.113,2.997)
  oval 0.2x1 smd: 17(-3.007,-4.133) 18(-2.607,-4.133) 19(-2.207,-4.133) 20(-1.807,-4.133) 21(-1.407,-4.133) 22(-1.007,-4.133) 23(-0.607,-4.133) 24(-0.207,-4.133) 25(0.193,-4.133) 26(0.593,-4.133) 27(0.993,-4.133) 28(1.393,-4.133) 29(1.793,-4.133) 30(2.193,-4.133) 31(2.593,-4.133) 32(2.993,-4.133) 49(2.993,4.117) 50(2.593,4.117) 51(2.193,4.117) 52(1.793,4.117) 53(1.393,4.117) 54(0.993,4.117) 55(0.593,4.117) 56(0.193,4.117) 57(-0.207,4.117) 58(-0.607,4.117) 59(-1.007,4.117) 60(-1.407,4.117) 61(-1.807,4.117) 62(-2.207,4.117) 63(-2.607,4.117) 64(-3.007,4.117)
  rect 6.2x6.2 smd: 65(0,0)
  rect 6.2x6.2 smd far side: 65(0,0)
  silkscreen extent -6.73,-6.6 6.57,6.6
R0603[1608] [mm] "Chip Resistor; Body 1.6 x 0.8 mm (LxW typ)"
  rect 1.1x1 smd: 1(-0.85,0) 2(0.85,0)
  silkscreen extent -1.8,-0.9 1.8,0.9
R0805[2012] [mm] "Chip Resistor; Body 2.0 x 1.3 mm (LxW typ)"
  rect 1.3x1.5 smd: 1(-0.95,0) 2(0.95,0)
  silkscreen extent -2.1,-1.25 2.1,1.25
RB5.0/10 [mm]
  oct 2.2x2.2 hole 1: 1(0,0)
  round 2.2 hole 1: 2(-5.08,0)
  silkscreen extent -8,-5.08 2.54,5.08
S7.62*1 [mm]
  oval 2.2x1.8 hole 1: 1(0,0) 2(7.62,0)
  silkscreen extent -1.4,-1.74 9.02,1.74
"S8 PACKAGE" [mil] "8-LEAD PLASTIC SO"
  rect 30x59.06 smd: 1(0,0) 2(50,0) 3(100,0) 4(150,0) 5(150,205) 6(100,205) 7(50,205) 8(0,205)
  silkscreen extent -20,36 170,170
SWITCH-4 [mm] "Switch; 4 Leads; Body 6 x 6 mm"
  rect 1.8x1.8 hole 1: 1(-3.25,-2.25)
  round 1.8 hole 1: 2(-3.25,2.25) 3(3.25,-2.25) 4(3.25,2.25)
  silkscreen extent -4.4,-3.4 4.4,3.4
TC3216-A [mm] "Capacitor, SM Tantalum; Body 3.2 x 1.6 mm (LxW typ)"
  rect 2x1.2 smd: 1(-1.4,0) 2(1.4,0)
  silkscreen extent -2.4,-1 1.7,1.1
TI-DCQ6_N [mm] "SOT223, 6-Leads, Body 6.5x3.5mm, Pitch 1.27mm, IPC Medium Density"
  rect 2.5x0.7 smd: 1(-3.025,2.54) 2(-3.025,1.27) 3(-3.025,0) 4(-3.025,-1.27) 5(-3.025,-2.54)
  rect 2.15x3.2 smd: 6(3.025,0)
  silkscreen extent -3.15,-3.3 1.65,3.57
TI-DRB8-2400X1650TP_V [mm] "SON, 8-Leads, Body 3x3mm, Pitch 0.65mm, Thermal Pad 2.4x1.65mm"
  rect 1.3x0.35 smd: 1(-1.73,0.97) 2(-1.73,0.32) 3(-1.73,-0.33) 4(-1.73,-0.98) 5(1.74,-0.98) 6(1.74,-0.33) 7(1.74,0.32) 8(1.74,0.97)
  rect 1.5x2.4 smd: 9(0,0)
  silkscreen extent -2.65,-1.5 2.6,1.5
TO-220AB [mm] "TO, Thru-Hole, Vertical, Heatsink Mounted; 3 In-Line Leads; Pitch 2.54 mm"
  rect 1.6x1.6 hole 1: 1(-2.54,0)
  round 1.6 hole 1: 2(0,0) 3(2.54,0)
  silkscreen extent -5.35,-1.85 5.35,2.85
VR_3386_Knob [mil]
  round 60 hole 30: 1(287.8,-188.19) 2(187.8,-275.98) 3(87.8,-188.19)
  silkscreen extent 0,-375 375,0

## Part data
C1 C2 C3 C16 C17 C18 C28: library part "Cap Pol1", "Polarized Capacitor (Radial)"
C4 C5 C6 C13 C14 C15 C19 C20 C21 C22 C23 C24 C29 C30 C54 C55 C56 C59 C60 C71 C72 C73 C74 C75 C76 C77 C78 C79 C80 C81 C82 C130 C131 C132 C133 C140 C141 C142 C143 C150 C151 C152 C153 C160 C161 C162 C163 C170 C171 C172 C173 C180 C181 C182 C183 C232 C233 C234 C235 C236 C237 C238 C239 C240 C241 C242 C243: library part CAP, "Capacitor"
C90 C91 CB8 CB9 CB10 CF1 CF2 CF3 CF5 CL2 CL13 CL14 CL16 CL20 CL26 CL36: library part "Capacitor Unpolarized", "CAP CER 0.1UF 16V X7R 0603"
CB1 CB2 CB3: library part "Capacitor Polarized", "CAP TANT 10UF 10V 10% 1206"
CB4 CB7 CL11 CL28 CL30 CL32 CL33 CL34 CL621: library part "Capacitor Unpolarized", "CAP CER 10000PF 10V X7R 0603"
CB5 CB6 CF4 CF6 CL12 CL27 CL31 CL420: library part "Capacitor Unpolarized", "CAP CER 2.2UF 10V X7R 0603"
CHIP: library part JOULE, "32-bit MCU with Double Motor Pre-driver"
CL1 CL15 CL17 CL21 CL22 CL23 CL24 CL35: library part "Capacitor Unpolarized", "CAP CER 4.7UF 10V X7S 0603"
CL3 CL29 CL38 CL39: library part "Capacitor Unpolarized", "CAP CER 1UF 16V X7R 0603"
CL4 CL5 CL6 CL7 CL8 CL9 CL10 CL25: library part "Capacitor Unpolarized", "Unpolarized Capacitor"
CL18 CL19: library part "Capacitor Unpolarized", "CAP CER 20PF 10V X7R 0603"
D1 D2 D3 D4 D5 D6 D7 D8 D9 D10 D11 D12: library part Diode, "Default Diode"
F1: library part Fuse
GND U1 U12 V1 V2 VBAT W1 W2: library part TP
L1: library part INDUCTOR
P1 P5 P8 P11 P13 P14: library part "Header 4", "Header, 4-Pin"
P2 P12 P15: library part "Header 2X2", "Header, 2-Pin, Dual row"
P3: library part "Header 13X2", "Header, 13-Pin, Dual row"
P4: library part "Header 5X2", "Header, 5-Pin, Dual row"
P7 P9: library part "Header 8X2", "Header, 8-Pin, Dual row"
P16 P19 P21 P22 P23 P25: library part "Header 6", "Header, 6-Pin"
P17 P18 P27 P28 P117: library part "Header 2", "Header, 2-Pin"
Q1 Q2 Q3 Q4 Q5 Q6 Q7 Q8 Q9 Q10 Q11 Q12: "HEXFET Power MOSFET"
R1 R2 R3 R4 R5 R6 R7 R8 R9 R10 R11 R12 R16 R17 R18 R19 R20 R21 R22 R23 R24 R25 R26 R27 R130 R131 R132 R133 R134 R135 R136 R137 R140 R141 R142 R143 R144 R145 R146 R147 R150 R151 R152 R153 R154 R155 R156 R157 R160 R161 R162 R163 R164 R165 R166 R167 R170 R171 R172 R173 R174 R175 R176 R177 R180 R181 R182 R183 R184 R185 R186 R187 R440 R441 R442 R443: library part RES2
R13 R14 R15 R28 R29 R30: library part RES1
R31 R32 R33 R37 R38 R39 R61 R63 R77: library part Resistor
R34 R41 R43 R52 R53 R54 R57 R58 R59: library part Resistor, "RES SMD 0.0OHM JUMPER 1/10W"
R35 R36 R62 R64 R68 R75 R168 R169: library part Resistor, "Resistor"
R66: library part Resistor, "RES SMD 100 OHM 1% 1/10W"
R93 R94: library part Resistor, "RES SMD 4.7K OHM 1% 1/10W"
S1 S3 S4 S5: library part SW-2
S2: "Switch Key"
U2: "Single Output High PSRR LDO, 1 A, Fixed 3.3 V Output, 2.7 to 5.5 V Input, 6-pin SOT-223 (DCQ), -40 to 125 degC, Green (RoHS & no Sb/Br)"
U3: "Single Output High PSRR LDO, 1 A, Fixed 1.3 V Output, 2.7 to 5.5 V Input, 8-pin SON (DRB), -40 to 85 degC, Green (RoHS & no Sb/Br)"
U4: "Ultralow Power High PSRR Voltage Reference, 1.2 V Output, 2.4 to 5.5 V Supply, Industrial, 3-pin SOT23 (RT-3), Reel"
U5: library part LT1461, "3.3V High Precision Voltage Reference"
U18: "LM5017 100-V, 600-mA Constant On-Time Synchronous Buck Regulator"
VR1 VR2: library part VR, "VR_3386_Knob"
Y1: "CRYSTAL 32.0000MHZ 20PF T/H"

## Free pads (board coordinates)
  round 2 smd: 0(66.1,55.9)

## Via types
v1: diameter 0.8, hole 0.5, Top Layer to Bottom Layer, tented both sides, 575 vias
v2: diameter 1, hole 0.6, Top Layer to Bottom Layer, 157 vias
v3: diameter 0.8, hole 0.5, Top Layer to Bottom Layer, 69 vias
v4: diameter 1, hole 0.6, Top Layer to Bottom Layer, tented both sides, 52 vias
v5: diameter 0.8, hole 0.4, Top Layer to Bottom Layer, 16 vias
v6: diameter 1.2, hole 0.7, Top Layer to Bottom Layer, tented both sides, 7 vias
v7: diameter 0.5, hole 0.3, Top Layer to Bottom Layer, 6 vias

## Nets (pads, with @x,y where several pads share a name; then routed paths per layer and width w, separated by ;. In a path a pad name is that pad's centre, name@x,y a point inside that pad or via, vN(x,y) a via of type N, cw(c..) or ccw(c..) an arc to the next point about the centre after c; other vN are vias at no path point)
ADC0: CHIP.3 P9.2 | length 39.9
  Top Layer w0.2: P9.2@34.232,106.2 36.91,103.522 36.91,97.29 46.52,87.68 54.19,87.68 58.423,83.447 CHIP.3@61.094,83.447
ADC1: CHIP.4 P9.4 | length 37.9
  Top Layer w0.2: P9.4@34.232,103.66 36.51,101.382 36.51,97.124 46.354,87.28 54.024,87.28 58.257,83.047 CHIP.4@61.094,83.047
ADC2: CHIP.5 P9.6 | length 35.9
  Top Layer w0.2: P9.6@34.232,101.12 36.11,99.242 36.11,96.959 46.189,86.88 53.859,86.88 58.091,82.647 CHIP.5@61.094,82.647
ADC3: CHIP.6 P9.8 | length 34.4
  Top Layer w0.2: P9.8@34.232,98.58 35.28,98.58 35.71,98.15 35.71,96.793 46.023,86.48 53.693,86.48 57.926,82.247 CHIP.6@61.094,82.247
ADC4: CHIP.7 P9.10 | length 32.7
  Top Layer w0.2: P9.10@34.232,96.04 35.897,96.04 45.857,86.08 53.527,86.08 57.76,81.847 CHIP.7@61.094,81.847
ADC5: CHIP.8 P9.12 | length 31.9
  Top Layer w0.2: P9.12@34.232,93.5 37.831,93.5 45.651,85.68 53.362,85.68 57.594,81.447 CHIP.8@61.094,81.447
ADC6: CHIP.9 P7.14 R93.2 | length 46
  Top Layer w0.2: v4(50.97,83.31) 50.99,83.29 55.15,83.29 57.393,81.047 CHIP.9@61.094,81.047
  Top Layer w0.381: P7.14@34.04,61.56 34.15,61.45 R93.2@37.3,61.45 40.348,61.45 44.651,65.754 48.454,65.754 50.2,67.5 50.2,74.36 v4@50.97,75.13
  Bottom Layer w0.381: v4(50.97,75.04) v4(50.97,83.31)
ADC7: CHIP.10 P7.16 R94.2 | length 45.6
  Top Layer w0.2: v4(52.23,82.48) 55.35,82.48 57.183,80.647 CHIP.10@61.094,80.647
  Top Layer w0.381: 48.685,65.163 50.9,67.378 50.9,72.01
  Top Layer w0.4: P7.16@34.04,59.02 34.27,59.25 R94.2@37.3,59.25 38.55,60.5 40.5,60.5 45.163,65.163 48.685,65.163 ; 50.9,72.01 50.9,73.01 v4(51.34,73.45)
  Bottom Layer w0.4: v4(51.34,73.45) 51.99,74.1 51.99,82.24 v4(52.23,82.48)
ADC8: CHIP.13 P7.2 | length 29
  Top Layer w0.2: P7.2@34.04,76.8 35.04,75.8 36.984,75.8 39.152,77.967 57.4,77.967 58.88,79.447 CHIP.13@61.094,79.447
ADC9: CHIP.14 P7.4 | length 29
  Top Layer w0.2: P7.4@34.04,74.26 34.999,75.219 36.969,75.219 39.317,77.567 57.566,77.567 59.046,79.047 CHIP.14@61.094,79.047
ADC10: CHIP.15 P7.6 R169.2 | length 95.9
  Top Layer w0.2: P7.6@34.04,71.72 35.04,70.72 35.69,70.72 36.04,71.07 36.04,73.526 39.682,77.167 57.732,77.167 59.212,78.647 CHIP.15@61.094,78.647
  Top Layer w0.381: v1(64.6,45.7) 64.873,45.427 R169.2@75.659,45.427
  Bottom Layer w0.381: P7.6@34.04,71.72 37.443,68.317 37.443,49.257 38.419,48.281 45.841,48.281 47.622,46.5 63.8,46.5 v1(64.6,45.7)
ADC11: CHIP.16 P7.8 R34.2 | length 78.9
  Top Layer w0.2: P7.8@34.04,69.18 35.12,70.26 35.82,70.26 36.44,70.88 36.44,73.36 39.847,76.767 57.897,76.767 59.377,78.247 CHIP.16@61.094,78.247
  Top Layer w0.381: v1(59.276,45.466) 59.315,45.427 R34.2@60.673,45.427
  Bottom Layer w0.381: P7.8@34.04,69.18 34.04,68.253 36.862,65.431 36.862,48.938 38.1,47.7 45.6,47.7 47.834,45.466 v1(59.276,45.466)
ADC12: CHIP.17 P7.10 R36.2 | length 66.5
  Top Layer w0.2: P7.10@34.04,66.64 35.07,65.61 35.784,65.61 36.88,66.706 36.88,73.116 40.114,76.35 61.863,76.35 62.213,76.7 CHIP.17@62.213,77.117
  Top Layer w0.381: R36.2@44.163,45.427 v1(44.163,46.863)
  Bottom Layer w0.381: P7.10@34.04,66.64 34.04,65.713 36.281,63.472 36.281,48.319 37.737,46.863 v1(44.163,46.863)
ADC13: CHIP.18 P7.12 R168.2 | length 58.6
  Top Layer w0.2: P7.12@34.04,64.1 35.02,65.079 35.819,65.079 37.28,66.54 37.28,72.95 40.28,75.95 62.029,75.95 62.613,76.534 CHIP.18@62.613,77.117
  Top Layer w0.381: R168.2@32.86,45.427 34.533,47.1 v4(34.6,47.1)
  Bottom Layer w0.381: P7.12@34.04,64.1 35.7,62.44 35.7,48.2 v4(34.6,47.1)
ADC14: CHIP.19 P9.14 | length 41.8
  Top Layer w0.2: P9.14@34.232,90.96 39.806,90.96 45.486,85.28 52.617,85.28 v4(53.807,84.09) ; v4(53.92,75.11) 54.29,75.48 62.124,75.48 63.013,76.368 CHIP.19@63.013,77.117
  Bottom Layer w0.381: v4(53.807,84.09) 53.807,75.223 v4(53.92,75.11)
